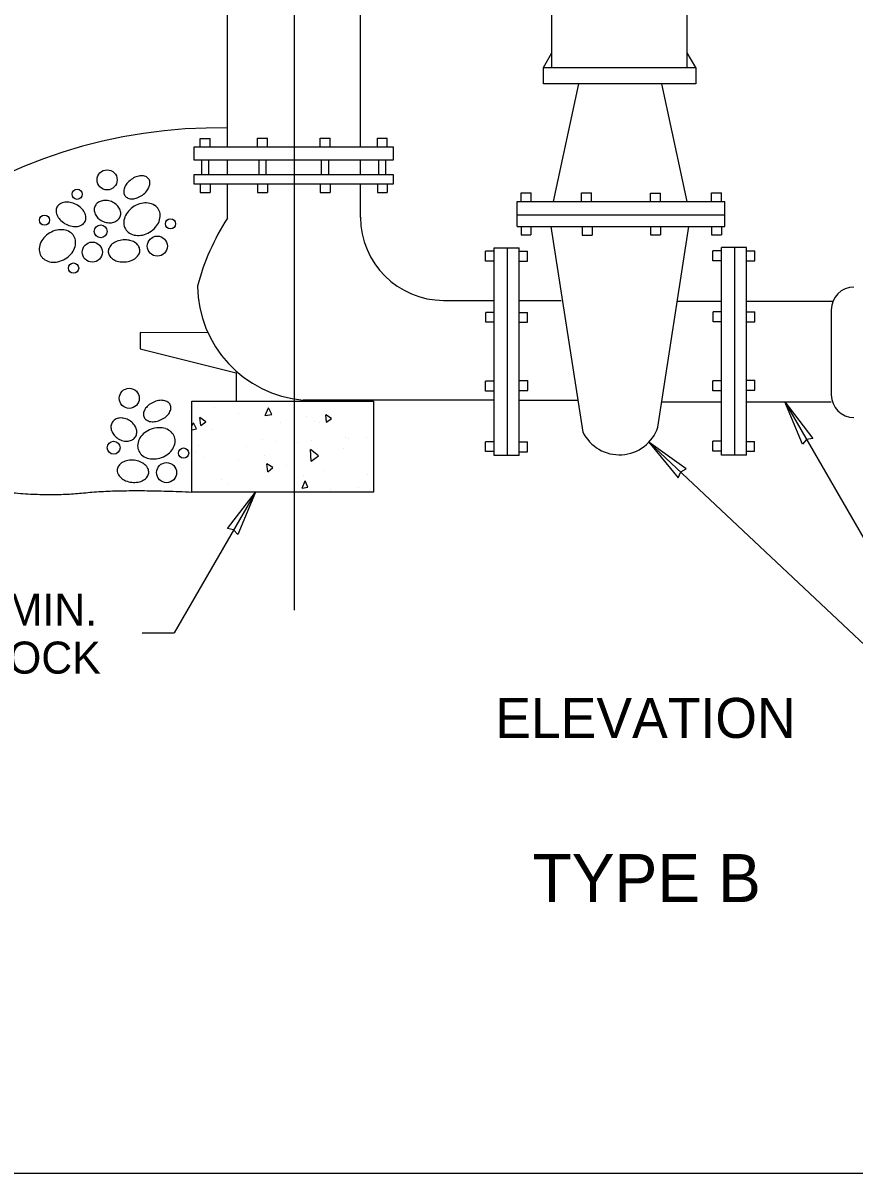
# Model space of a CAD drawing. Extents: x 99862 to 103151, y 100000 to 102076.
# Drawn here: x 101687 to 102102, y 100000 to 100574 of the extents above; entities that cross this region are included whole.
import ezdxf

# ---------------------------------------------------------------- set-up
doc = ezdxf.new("R2010")
doc.units = 0
for name, color, linetype in [('Level 1', 7, 'Continuous'), ('Level 10', 7, 'Continuous'), ('Level 15', 7, 'Continuous'), ('Level 17', 7, 'Continuous'), ('Level 18', 7, 'Continuous'), ('Level 20', 7, 'Continuous'), ('Level 6', 7, 'Continuous')]:
    doc.layers.add(name, color=color, linetype=linetype)

msp = doc.modelspace()

# ---------------------------------------------------------------- linework, layer by layer
at = {"layer": 'Level 1'}
msp.add_line((102018.71, 100484.73), (102006.2, 100543.53), dxfattribs=at)
msp.add_lwpolyline([(99862, 99999.5), (103151, 99999.5), (103151, 102075.5), (99862, 102075.5)], close=True, dxfattribs=at)
msp.add_arc((101784.76, 100265.79), 255.78, 89.02946, 162.96913, dxfattribs=at)
msp.add_open_spline([(101540.14, 100340.7), (101572.89, 100341.52), (101607.18, 100338.57), (101654.79, 100342.57), (101698.15, 100337.27), (101736.73, 100341.25), (101771.26, 100339.65)], degree=2, dxfattribs=at)
at = {"layer": 'Level 10'}
for p, q in [((101782.7, 100381.67), (101782.7, 100381.67)), ((101807.99, 100377.95), (101809.55, 100381.67)), ((101811.19, 100378.47), (101809.55, 100381.67)), ((101771.26, 100372.61), (101772.06, 100374.21)), ((101773.66, 100371.31), (101772.06, 100374.21)), ((101775.79, 100372.86), (101775.26, 100376.86)), ((101778.2, 100374.73), (101775.26, 100376.86)), ((101775.79, 100372.86), (101778.2, 100374.73)), ((101794.41, 100379), (101794.41, 100379)), ((101807.99, 100377.95), (101811.19, 100378.47)), ((101815.69, 100374.48), (101815.69, 100374.48)), ((101828.46, 100377.42), (101828.46, 100377.42)), ((101832.46, 100375.01), (101832.46, 100375.01)), ((101835.09, 100374.48), (101835.09, 100374.48)), ((101838.58, 100374.48), (101838.26, 100378.18)), ((101840.98, 100376.33), (101838.26, 100378.18)), ((101838.58, 100374.48), (101840.98, 100376.33)), ((101771.26, 100370.76), (101773.66, 100371.31)), ((101781.4, 100370.76), (101781.4, 100370.76)), ((101774.74, 100363.05), (101774.74, 100363.05)), ((101806.38, 100365.98), (101806.38, 100365.98)), ((101813.81, 100364.93), (101813.81, 100364.93)), ((101824.2, 100364.35), (101824.2, 100364.35)), ((101831.11, 100365.42), (101831.11, 100365.42)), ((101848.14, 100367.06), (101848.14, 100367.06)), ((101849.74, 100366.51), (101849.74, 100366.51)), ((101858.78, 100366.78), (101858.78, 100366.78)), ((101773.14, 100360.08), (101773.14, 100360.08)), ((101777.64, 100356.91), (101777.64, 100356.91)), ((101798.68, 100362.25), (101798.68, 100362.25)), ((101807.7, 100358), (101807.7, 100358)), ((101830.84, 100355.06), (101830.59, 100360.92)), ((101834.6, 100357.71), (101830.59, 100360.92)), ((101830.84, 100355.06), (101834.6, 100357.71)), ((101847.09, 100361.45), (101847.09, 100361.45)), ((101794.66, 100355.35), (101794.66, 100355.35)), ((101809.31, 100349.76), (101808.79, 100353.73)), ((101811.69, 100351.88), (101808.79, 100353.73)), ((101809.31, 100349.76), (101811.69, 100351.88)), ((101818.35, 100352.93), (101818.35, 100352.93)), ((101786.15, 100346.03), (101786.15, 100346.03)), ((101826.33, 100341.52), (101827.94, 100345.22)), ((101827.14, 100347.91), (101827.14, 100347.91)), ((101829.26, 100342.02), (101827.94, 100345.22)), ((101837.21, 100350.28), (101837.21, 100350.28)), ((101859.05, 100348.4), (101859.05, 100348.4)), ((101789.64, 100343.9), (101789.64, 100343.9)), ((101813.04, 100339.9), (101813.04, 100339.9)), ((101826.33, 100341.52), (101829.26, 100342.02)), ((101828.99, 100339.65), (101828.99, 100339.65)), ((101830.59, 100339.9), (101830.59, 100339.9)), ((101840.43, 100340.97), (101840.43, 100340.97)), ((101854.51, 100341.77), (101854.51, 100341.77)), ((101860.13, 100340.45), (101860.13, 100340.45))]:
    msp.add_line(p, q, dxfattribs=at)
for centre, radius in [((101728.92, 100495.58), 5.02), ((101713.97, 100488.4), 2.54), ((101697.62, 100475.45), 2.54), ((101725.73, 100469.86), 3.22), ((101760.61, 100473.65), 2.54), ((101754.03, 100462.49), 5.02), ((101721.54, 100459.5), 5.02), ((101712.18, 100451.53), 2.54), ((101740.01, 100386.47), 5.02), ((101732.18, 100361.77), 3.22), ((101767.17, 100359.12), 2.54), ((101758.66, 100349.35), 5.02)]:
    msp.add_circle(centre, radius, dxfattribs=at)
for centre, radius, start, end in [((101747.44, 100486.85), 11.02, 126.08477, 141.32523), ((101747.44, 100486.85), 11.02, 110.84431, 126.08477), ((101746.31, 100489.83), 7.84, 92.74951, 110.84431), ((101746.2, 100492.15), 5.51, 68.28483, 92.74951), ((101747.05, 100494.28), 3.22, 36.08477, 68.28483), ((101747.05, 100494.28), 3.22, 3.88471, 36.08477), ((101742.78, 100489.66), 5.51, 159.42002, 183.88471), ((101740.49, 100489.5), 3.22, 183.88471, 216.08477), ((101744.96, 100488.84), 7.84, 141.32523, 159.42002), ((101740.1, 100496.93), 11.02, 306.08477, 321.32523), ((101742.58, 100494.94), 7.84, 321.32523, 339.42002), ((101744.76, 100494.12), 5.51, 339.42002, 3.88471), ((101707.38, 100480.18), 3.92, 122.21424, 152.88878), ((101708.56, 100478.3), 6.14, 97.81622, 122.21424), ((101708.86, 100476.14), 8.32, 79.02153, 97.81622), ((101708.3, 100473.25), 11.27, 62.88878, 79.02153), ((101708.3, 100473.25), 11.27, 46.75604, 62.88878), ((101726.66, 100480.69), 4.21, 130.69622, 158.66336), ((101727.6, 100479.6), 5.65, 106.62121, 130.69623), ((101727.98, 100478.31), 6.99, 86.57049, 106.62121), ((101727.88, 100476.56), 8.75, 68.66336, 86.57049), ((101727.88, 100476.56), 8.75, 50.75623, 68.66336), ((101728.99, 100477.92), 6.99, 30.70551, 50.75623), ((101740.49, 100489.5), 3.22, 216.08477, 248.28483), ((101741.34, 100491.63), 5.51, 248.28483, 272.74951), ((101741.23, 100493.95), 7.84, 272.74951, 290.84431), ((101748.73, 100471.93), 12.2, 102.54735, 120.55568), ((101740.1, 100496.93), 11.02, 290.84431, 306.08477), ((101748.21, 100474.27), 9.8, 82.43038, 102.54735), ((101748.45, 100476.1), 7.95, 58.38014, 82.43038), ((101707.38, 100480.18), 3.92, 152.88878, 183.56333), ((101709.6, 100480.32), 6.14, 183.56333, 207.96135), ((101711.53, 100481.34), 8.32, 207.96135, 226.75604), ((101710.32, 100475.39), 8.32, 27.96135, 46.75604), ((101712.25, 100476.42), 6.14, 3.56333, 27.96135), ((101726.66, 100480.69), 4.21, 158.66336, 186.63049), ((101728.09, 100480.86), 5.65, 186.63049, 210.70551), ((101729.25, 100481.55), 6.99, 210.70551, 230.75623), ((101730.15, 100478.6), 5.65, 6.63049, 30.70551), ((101731.58, 100478.77), 4.21, 338.66336, 6.63049), ((101746.93, 100473.52), 9.8, 138.56401, 158.68099), ((101748.73, 100471.93), 12.2, 120.55568, 138.56401), ((101749.49, 100477.79), 5.97, 30.55568, 58.38014), ((101749.49, 100477.79), 5.97, 2.73122, 30.55568), ((101747.51, 100477.7), 7.95, 338.68099, 2.73122), ((101713.55, 100483.49), 11.27, 226.75604, 242.88878), ((101713.55, 100483.49), 11.27, 242.88878, 259.02152), ((101712.98, 100480.6), 8.32, 259.02152, 277.81622), ((101713.28, 100478.43), 6.14, 277.81622, 302.21424), ((101714.46, 100476.55), 3.92, 302.21424, 332.88878), ((101714.46, 100476.55), 3.92, 332.88878, 3.56333), ((101730.36, 100482.91), 8.75, 230.75623, 248.66336), ((101730.36, 100482.91), 8.75, 248.66336, 266.57049), ((101730.25, 100481.15), 6.99, 266.57049, 286.62121), ((101730.64, 100479.86), 5.65, 286.62121, 310.69623), ((101731.58, 100478.77), 4.21, 310.69623, 338.66336), ((101745.21, 100474.19), 7.95, 158.68099, 182.73122), ((101743.23, 100474.1), 5.97, 182.73122, 210.55568), ((101743.99, 100479.96), 12.2, 300.55568, 318.56401), ((101745.79, 100478.37), 9.8, 318.56401, 338.68099), ((101704.67, 100460.16), 9.8, 138.56401, 158.68099), ((101706.47, 100458.57), 12.2, 120.55568, 138.56401), ((101706.47, 100458.57), 12.2, 102.54735, 120.55568), ((101705.95, 100460.92), 9.8, 82.43038, 102.54735), ((101706.19, 100462.75), 7.95, 58.38014, 82.43038), ((101707.23, 100464.44), 5.97, 30.55568, 58.38014), ((101707.23, 100464.44), 5.97, 2.73122, 30.55568), ((101743.23, 100474.1), 5.97, 210.55568, 238.38014), ((101744.27, 100475.78), 7.95, 238.38014, 262.43038), ((101744.51, 100477.61), 9.8, 262.43038, 282.54735), ((101743.99, 100479.96), 12.2, 282.54735, 300.55568), ((101702.95, 100460.84), 7.95, 158.68099, 182.73122), ((101700.97, 100460.74), 5.97, 182.73122, 210.55568), ((101703.53, 100465.01), 9.8, 318.56401, 338.68099), ((101705.25, 100464.34), 7.95, 338.68099, 2.73122), ((101733.42, 100459.8), 3.92, 153.66865, 184.34319), ((101735.41, 100458.81), 6.14, 129.27062, 153.66865), ((101736.8, 100457.12), 8.32, 110.47593, 129.27062), ((101737.83, 100454.36), 11.27, 94.34319, 110.47593), ((101737.83, 100454.36), 11.27, 78.21045, 94.34319), ((101738.43, 100457.24), 8.32, 59.41576, 78.21045), ((101739.54, 100459.12), 6.14, 35.01773, 59.41576), ((101741.36, 100460.4), 3.92, 4.34319, 35.01773), ((101741.36, 100460.4), 3.92, 333.66865, 4.34319), ((101700.97, 100460.74), 5.97, 210.55568, 238.38014), ((101702.01, 100462.43), 7.95, 238.38014, 262.43038), ((101702.25, 100464.26), 9.8, 262.43038, 282.54735), ((101701.73, 100466.6), 12.2, 282.54735, 300.55568), ((101701.73, 100466.6), 12.2, 300.55568, 318.56401), ((101733.42, 100459.8), 3.92, 184.34319, 215.01773), ((101735.24, 100461.07), 6.14, 215.01773, 239.41576), ((101736.35, 100462.95), 8.32, 239.41576, 258.21045), ((101736.96, 100465.84), 11.27, 258.21045, 274.34319), ((101736.96, 100465.84), 11.27, 274.34319, 290.47593), ((101737.99, 100463.08), 8.32, 290.47593, 309.27062), ((101739.37, 100461.38), 6.14, 309.27062, 333.66865), ((101756.06, 100377.63), 7.84, 82.22884, 100.32364), ((101752.56, 100378.11), 5.51, 148.89935, 173.36404), ((101754.55, 100376.91), 7.84, 130.80456, 148.89936), ((101756.63, 100374.5), 11.02, 115.5641, 130.80456), ((101756.63, 100374.5), 11.02, 100.32364, 115.5641), ((101756.37, 100379.94), 5.51, 57.76416, 82.22884), ((101757.6, 100381.88), 3.22, 25.5641, 57.76416), ((101755.32, 100382.14), 5.51, 328.89935, 353.36404), ((101757.6, 100381.88), 3.22, 353.36404, 25.5641), ((101735.07, 100372.24), 4.21, 148.14269, 176.10982), ((101735.07, 100372.24), 4.21, 120.17556, 148.14269), ((101735.79, 100371), 5.65, 96.10054, 120.17556), ((101735.94, 100369.66), 6.99, 76.04982, 96.10054), ((101735.51, 100367.95), 8.75, 58.14269, 76.04982), ((101735.51, 100367.95), 8.75, 40.23556, 58.14269), ((101750.28, 100378.38), 3.22, 173.36404, 205.5641), ((101750.28, 100378.38), 3.22, 205.5641, 237.76416), ((101751.5, 100380.32), 5.51, 237.76416, 262.22884), ((101751.82, 100382.62), 7.84, 262.22884, 280.32364), ((101751.25, 100385.76), 11.02, 280.32364, 295.5641), ((101751.25, 100385.76), 11.02, 295.5641, 310.80456), ((101753.33, 100383.35), 7.84, 310.80456, 328.89936), ((101736.51, 100372.15), 5.65, 176.10983, 200.18484), ((101737.77, 100372.61), 6.99, 200.18484, 220.23556), ((101736.85, 100369.09), 6.99, 20.18484, 40.23556), ((101739.56, 100369.46), 4.21, 328.14269, 356.10982), ((101738.12, 100369.55), 5.65, 356.10983, 20.18484), ((101753.69, 100361.49), 9.8, 128.04334, 148.16032), ((101755.17, 100359.6), 12.2, 110.03501, 128.04334), ((101755.17, 100359.6), 12.2, 92.02668, 110.03501), ((101755.09, 100362), 9.8, 71.90971, 92.02668), ((101755.66, 100363.75), 7.95, 47.85948, 71.90971), ((101756.99, 100365.22), 5.97, 20.03501, 47.85948), ((101739.11, 100373.74), 8.75, 220.23556, 238.14269), ((101739.11, 100373.74), 8.75, 238.14269, 256.04982), ((101738.69, 100372.04), 6.99, 256.04982, 276.10054), ((101738.83, 100370.7), 5.65, 276.10054, 300.17556), ((101739.56, 100369.46), 4.21, 300.17556, 328.14269), ((101750.16, 100362.73), 5.97, 172.21055, 200.03501), ((101752.12, 100362.46), 7.95, 148.16032, 172.21055), ((101755.03, 100365.49), 7.95, 328.16032, 352.21055), ((101756.99, 100365.22), 5.97, 352.21055, 20.03501), ((101750.16, 100362.73), 5.97, 200.03501, 227.85948), ((101751.49, 100364.2), 7.95, 227.85948, 251.90971), ((101751.98, 100368.36), 12.2, 272.02668, 290.03501), ((101751.98, 100368.36), 12.2, 290.03501, 308.04334), ((101753.46, 100366.47), 9.8, 308.04334, 328.16032), ((101737.91, 100350.46), 3.92, 143.14798, 173.82252), ((101739.68, 100349.13), 6.14, 118.74996, 143.14798), ((101740.73, 100347.22), 8.32, 99.95526, 118.74996), ((101741.24, 100344.31), 11.27, 83.82252, 99.95526), ((101741.24, 100344.31), 11.27, 67.68978, 83.82252), ((101742.36, 100347.04), 8.32, 48.89509, 67.68978), ((101743.8, 100348.69), 6.14, 24.49706, 48.89509), ((101752.06, 100365.96), 9.8, 251.90971, 272.02668), ((101745.82, 100349.61), 3.92, 353.82252, 24.49706), ((101737.91, 100350.46), 3.92, 173.82252, 204.49706), ((101739.93, 100351.38), 6.14, 204.49706, 228.89509), ((101741.36, 100353.03), 8.32, 228.89509, 247.68978), ((101742.48, 100355.76), 11.27, 247.68978, 263.82252), ((101742.99, 100352.85), 8.32, 279.95526, 298.74996), ((101744.04, 100350.94), 6.14, 298.74996, 323.14798), ((101745.82, 100349.61), 3.92, 323.14798, 353.82252), ((101742.48, 100355.76), 11.27, 263.82252, 279.95526)]:
    msp.add_arc(centre, radius, start, end, dxfattribs=at)
at = {"layer": 'Level 15'}
for p, q in [((101822.33, 101138.38), (101822.33, 100280.71)), ((102067.56, 100384.76), (102113.17, 100305.77)), ((101803.01, 100339.65), (101762.39, 100269.28)), ((101746.39, 100269.28), (101762.39, 100269.28))]:
    msp.add_line(p, q, dxfattribs=at)
for points in [[(102067.56, 100384.76), (102081.56, 100366.48), (102078.45, 100365.91), (102076.39, 100363.5)], [(101803.01, 100339.65), (101794.18, 100318.38), (101792.13, 100320.79), (101789.01, 100321.37)]]:
    msp.add_lwpolyline(points, close=True, dxfattribs=at)
at = {"layer": 'Level 17'}
msp.add_lwpolyline([(101771.26, 100339.65), (101771.26, 100385.13), (101861.98, 100385.13), (101861.98, 100339.65)], close=True, dxfattribs=at)
at = {"layer": 'Level 18'}
for p, q in [((101951.21, 100551.77), (101951.21, 100607.08)), ((102018.78, 100551.77), (102018.78, 100607.08)), ((101946.96, 100551.77), (101951.21, 100558.98)), ((102023.04, 100551.77), (102018.78, 100558.98)), ((101952.05, 100484.73), (101964.58, 100543.53)), ((101872.06, 100511.98), (101772.34, 100511.98)), ((101772.34, 100511.98), (101772.34, 100505.61)), ((101775.49, 100516.33), (101780.45, 100516.33)), ((101775.49, 100511.96), (101775.49, 100516.33)), ((101780.45, 100511.96), (101780.45, 100516.33)), ((101804.13, 100516.46), (101809.09, 100516.46)), ((101804.13, 100512.05), (101804.13, 100516.46)), ((101809.09, 100512.05), (101809.09, 100516.46)), ((101835.4, 100516.46), (101840.36, 100516.46)), ((101835.4, 100512.05), (101835.4, 100516.46)), ((101840.36, 100512.05), (101840.36, 100516.46)), ((101863.99, 100516.4), (101868.95, 100516.4)), ((101863.99, 100511.98), (101863.99, 100516.4)), ((101868.95, 100511.98), (101868.95, 100516.4)), ((101872.06, 100505.61), (101872.06, 100511.98)), ((101772.34, 100505.61), (101872.06, 100505.61)), ((101776.19, 100498.15), (101776.19, 100505.61)), ((101779.74, 100498.15), (101779.74, 100505.61)), ((101804.84, 100498.15), (101804.84, 100505.61)), ((101808.39, 100498.15), (101808.39, 100505.61)), ((101836.1, 100498.15), (101836.1, 100505.61)), ((101839.65, 100498.15), (101839.65, 100505.61)), ((101864.69, 100498.15), (101864.69, 100505.61)), ((101868.24, 100498.15), (101868.24, 100505.61)), ((101775.49, 100493.65), (101775.49, 100489.26)), ((101775.49, 100489.26), (101780.45, 100489.26)), ((101780.45, 100493.65), (101780.45, 100489.26)), ((101789.08, 100476.35), (101789.08, 100493.65)), ((101804.13, 100493.65), (101804.13, 100489.26)), ((101804.13, 100489.26), (101809.09, 100489.26)), ((101809.09, 100493.65), (101809.09, 100489.26)), ((101835.4, 100493.65), (101835.4, 100489.26)), ((101835.4, 100489.26), (101840.36, 100489.26)), ((101840.36, 100493.65), (101840.36, 100489.26)), ((101855.6, 100476.87), (101855.6, 100493.65)), ((101863.99, 100493.65), (101863.99, 100489.26)), ((101863.99, 100489.26), (101868.95, 100489.26)), ((101868.95, 100493.65), (101868.95, 100489.26)), ((101935.83, 100489.13), (101940.8, 100489.13)), ((101935.83, 100484.73), (101935.83, 100489.13)), ((101940.8, 100484.73), (101940.8, 100489.13)), ((101966.03, 100489.05), (101970.99, 100489.05)), ((101966.03, 100484.73), (101966.03, 100489.05)), ((101970.99, 100484.73), (101970.99, 100489.05)), ((102000.44, 100488.92), (102005.4, 100488.92)), ((102000.44, 100484.82), (102000.44, 100488.92)), ((102005.4, 100484.73), (102005.4, 100488.92)), ((102030.93, 100484.73), (102030.93, 100489.05)), ((102030.93, 100489.05), (102035.9, 100489.05)), ((102035.9, 100484.73), (102035.9, 100489.05)), ((101933.91, 100484.73), (102037.65, 100484.73)), ((101933.91, 100472.25), (101933.91, 100484.73)), ((102037.65, 100472.25), (102037.65, 100484.73)), ((101933.91, 100478.1), (102037.65, 100478.1)), ((101933.91, 100472.25), (102037.65, 100472.25)), ((101935.76, 100472.25), (101935.76, 100468.17)), ((101940.74, 100472.25), (101940.74, 100468.17)), ((101950.73, 100472.25), (101966.66, 100369.62)), ((101966.39, 100472.25), (101966.39, 100468.02)), ((101971.35, 100472.25), (101971.35, 100468.02)), ((102000.44, 100472.25), (102000.44, 100468.13)), ((102004.14, 100372.02), (102019.68, 100472.25)), ((102005.4, 100472.25), (102005.4, 100468.13)), ((102030.93, 100472.25), (102030.93, 100468.11)), ((102035.9, 100472.25), (102035.9, 100468.11)), ((101935.76, 100468.17), (101940.74, 100468.17)), ((101966.39, 100468.02), (101971.35, 100468.02)), ((102000.44, 100468.13), (102005.4, 100468.13)), ((102030.93, 100468.11), (102035.9, 100468.11)), ((101922.39, 100357.93), (101922.39, 100461.66)), ((101922.39, 100461.66), (101934.88, 100461.66)), ((101929.01, 100357.93), (101929.01, 100461.66)), ((101934.88, 100357.93), (101934.88, 100461.66)), ((102035.95, 100460.12), (102031.64, 100460.12)), ((102031.64, 100455.16), (102031.64, 100460.12)), ((102035.95, 100358.15), (102035.95, 100461.88)), ((102048.45, 100461.88), (102035.95, 100461.88)), ((102042.59, 100358.15), (102042.59, 100461.88)), ((102048.45, 100358.15), (102048.45, 100461.88)), ((102048.45, 100460.12), (102052.58, 100460.12)), ((102052.58, 100455.16), (102052.58, 100460.12)), ((101922.39, 100459.91), (101918.06, 100459.91)), ((101918.06, 100454.95), (101918.06, 100459.91)), ((101922.39, 100454.95), (101918.06, 100454.95)), ((101934.88, 100459.91), (101939.01, 100459.91)), ((101934.88, 100454.95), (101939.01, 100454.95)), ((101939.01, 100454.95), (101939.01, 100459.91)), ((102035.95, 100455.16), (102031.64, 100455.16)), ((102048.45, 100455.16), (102052.58, 100455.16)), ((101897.08, 100435.4), (101922.39, 100435.4)), ((101934.88, 100435.4), (101955.75, 100435.4)), ((102013.91, 100435.02), (102035.95, 100435.02)), ((101918.19, 100424.45), (101918.19, 100429.41)), ((101922.39, 100429.41), (101918.19, 100429.41)), ((101934.88, 100429.41), (101938.98, 100429.41)), ((101938.98, 100424.45), (101938.98, 100429.41)), ((102031.76, 100424.66), (102031.76, 100429.62)), ((102035.95, 100429.62), (102031.76, 100429.62)), ((102048.45, 100429.62), (102052.55, 100429.62)), ((102052.55, 100424.66), (102052.55, 100429.62)), ((101922.29, 100424.45), (101918.19, 100424.45)), ((101934.88, 100424.45), (101938.98, 100424.45)), ((102035.86, 100424.66), (102031.76, 100424.66)), ((102048.45, 100424.66), (102052.55, 100424.66)), ((101918.06, 100390.03), (101918.06, 100395)), ((101922.39, 100395), (101918.06, 100395)), ((101934.88, 100395.37), (101939.1, 100395.37)), ((101939.1, 100390.4), (101939.1, 100395.37)), ((102031.64, 100390.25), (102031.64, 100395.21)), ((102035.95, 100395.21), (102031.64, 100395.21)), ((102048.45, 100395.58), (102052.68, 100395.58)), ((102052.68, 100390.62), (102052.68, 100395.58)), ((101922.39, 100385.62), (101826.89, 100385.62)), ((101922.39, 100390.03), (101918.06, 100390.03)), ((101934.88, 100390.4), (101939.1, 100390.4)), ((101934.88, 100385.62), (101964.18, 100385.62)), ((102035.95, 100390.25), (102031.64, 100390.25)), ((102048.45, 100390.62), (102052.68, 100390.62)), ((102006.11, 100384.76), (102035.95, 100384.76)), ((101917.98, 100359.85), (101917.98, 100364.81)), ((101922.39, 100364.81), (101917.98, 100364.81)), ((101934.88, 100364.75), (101938.95, 100364.75)), ((101938.95, 100359.78), (101938.95, 100364.75)), ((102031.55, 100360.06), (102031.55, 100365.02)), ((102035.95, 100365.02), (102031.55, 100365.02)), ((102048.45, 100364.96), (102052.51, 100364.96)), ((102052.51, 100360), (102052.51, 100364.96)), ((101922.39, 100359.85), (101917.98, 100359.85)), ((101934.88, 100357.93), (101922.39, 100357.93)), ((101934.88, 100359.78), (101938.95, 100359.78)), ((102035.95, 100360.06), (102031.55, 100360.06)), ((102048.45, 100358.15), (102035.95, 100358.15)), ((102048.45, 100360), (102052.51, 100360))]:
    msp.add_line(p, q, dxfattribs=at)
for points in [[(101946.96, 100543.53), (101946.96, 100551.77), (102023.04, 100551.77), (102023.04, 100543.53)], [(101872.06, 100493.65), (101872.06, 100498.15), (101772.34, 100498.15), (101772.34, 100493.65)]]:
    msp.add_lwpolyline(points, close=True, dxfattribs=at)
msp.add_lwpolyline([(101779.28, 100419.17), (101745.48, 100419.42), (101745.48, 100411.16), (101793.34, 100399.22), (101793.34, 100385.13)], dxfattribs=at)
for centre, radius, start, end in [((101886.36, 100413.16), 116.05, 146.94936, 165.35136), ((101897.14, 100476.96), 41.56, 180, 270), ((101831.86, 100443.19), 57.78, 180.67379, 265.06119), ((101984.91, 100378.6), 20.34, 206.05486, 341.14368)]:
    msp.add_arc(centre, radius, start, end, dxfattribs=at)
at = {"layer": 'Level 20'}
msp.add_line((101999.71, 100364.65), (102113.17, 100257.77), dxfattribs=at)
msp.add_lwpolyline([(101999.71, 100364.65), (102014.28, 100346.83), (102015.56, 100349.72), (102018.37, 100351.17)], close=True, dxfattribs=at)
at = {"layer": 'Level 6'}
for p, q in [((101789.08, 100511.98), (101789.08, 100802.41)), ((101855.6, 100511.98), (101855.6, 100802.41)), ((101789.08, 100498.15), (101789.08, 100505.61)), ((101855.6, 100498.15), (101855.6, 100505.61)), ((102048.45, 100435.02), (102091.68, 100435.02)), ((102090.81, 100430.67), (102090.81, 100388.21)), ((102048.45, 100384.76), (102090.81, 100384.76))]:
    msp.add_line(p, q, dxfattribs=at)
for centre, start, end in [((102102.15, 100430.67), 90, 180), ((102102.15, 100388.23), 180, 270)]:
    msp.add_arc(centre, 11.35, start, end, dxfattribs=at)

# ---------------------------------------------------------------- texts
at = {"layer": 'Level 20'}
for s, height, p in [('12" × 12" × 4" MIN.', 16, (101541.78, 100272.95)), ('CONCRETE BLOCK', 16, (101527.24, 100248.95)), ('ELEVATION', 20, (101922.88, 100216.82)), ('TYPE B', 24, (101941.48, 100134.82))]:
    msp.add_text(s, height=height, dxfattribs=at).set_placement(p)

doc.saveas('drawing.dxf')
